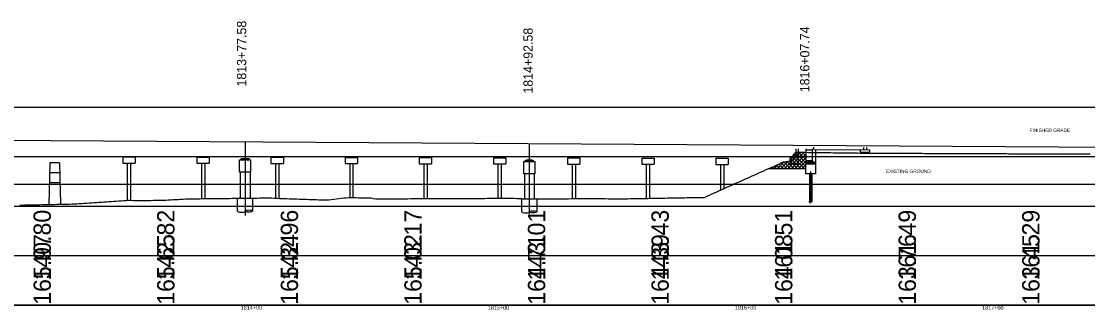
# Model space of a CAD drawing. Extents: x 2126510 to 2136144, y 865066 to 868066.
# Drawn here: x 2129755.8 to 2130187.2, y 866612.1 to 866728.8 of the extents above; entities that cross this region are included whole.
import ezdxf

# ---------------------------------------------------------------- set-up
doc = ezdxf.new("R2010")
doc.units = 0
for name, color, linetype in [('RD_DTM_BkLn1', 7, 'Continuous'), ('RD_EX_Bldg', 7, 'Continuous'), ('RD_EX_Bridge', 7, 'Continuous'), ('RD_EX_DR_Pipe', 7, 'Continuous'), ('RD_EX_GuardRail', 7, 'Continuous'), ('RD_EX_H2O', 7, 'Continuous'), ('RD_EX_Misc', 7, 'Continuous'), ('RD_EX_Misc_Golf_Fairway', 7, 'Continuous'), ('RD_HC_Data', 7, 'Continuous'), ('RD_HC_txCode', 7, 'Continuous')]:
    doc.layers.add(name, color=color, linetype=linetype)

msp = doc.modelspace()

# ---------------------------------------------------------------- linework, layer by layer
at = {"layer": 'RD_DTM_BkLn1'}
for p, q in [((2130076.46, 866676.93), (2130076.46, 866677.93)), ((2130096.46, 866677.81), (2130096.46, 866676.81)), ((2130097.71, 866677.81), (2130097.71, 866676.81)), ((2129848.04, 866673.11), (2129844.54, 866673.11)), ((2129844.54, 866673.11), (2129844.54, 866672.78)), ((2129844.96, 866673.11), (2129847.63, 866673.11)), ((2129848.04, 866672.78), (2129848.04, 866673.11)), ((2129962.63, 866672.68), (2129959.96, 866672.68)), ((2130076.46, 866676.93), (2130098.96, 866676.79)), ((2130095.21, 866676.82), (2130095.21, 866675.82)), ((2130095.21, 866675.82), (2130098.96, 866675.79)), ((2130098.96, 866676.79), (2130098.96, 866675.79)), ((2129963.04, 866672.39), (2129959.54, 866672.39)), ((2129959.54, 866672.39), (2129959.54, 866672.06)), ((2129959.96, 866672.39), (2129962.63, 866672.39)), ((2129963.04, 866672.06), (2129963.04, 866672.39)), ((2130076.88, 866671.67), (2130073.38, 866671.67)), ((2130073.38, 866671.67), (2130073.38, 866671.09)), ((2130076.46, 866671.96), (2130073.79, 866671.96)), ((2130073.79, 866671.96), (2130073.79, 866671.67)), ((2130073.79, 866671.67), (2130076.46, 866671.67)), ((2130076.46, 866671.67), (2130076.46, 866671.96)), ((2130076.88, 866671.09), (2130076.88, 866671.67)), ((2129844.29, 866667.78), (2129844.29, 866657.21)), ((2129848.29, 866667.78), (2129848.29, 866657.25)), ((2129959.29, 866667.06), (2129959.29, 866656.94)), ((2129963.29, 866667.06), (2129963.29, 866656.94))]:
    msp.add_line(p, q, dxfattribs=at)
for points in [[(2129844.04, 866672.78), (2129848.54, 866672.78), (2129848.54, 866667.78), (2129844.04, 866667.78)], [(2129959.04, 866672.06), (2129963.54, 866672.06), (2129963.54, 866667.06), (2129959.04, 866667.06)], [(2130073.13, 866671.09), (2130077.13, 866671.09), (2130077.13, 866667.09), (2130073.13, 866667.09)]]:
    msp.add_lwpolyline(points, close=True, dxfattribs=at)
for points in [[(2129843.29, 866651.99), (2129843.29, 866657.23), (2129849.29, 866657.23), (2129849.29, 866651.99)], [(2129958.29, 866651.7), (2129958.29, 866656.94), (2129964.29, 866656.94), (2129964.29, 866651.7)]]:
    msp.add_lwpolyline(points, dxfattribs=at)
for centre in [(2129844.79, 866651.99), (2129959.79, 866651.7)]:
    msp.add_ellipse(centre, major_axis=(-1.5, 0), ratio=0.310397, start_param=0, end_param=3.141593, dxfattribs=at)
for centre in [(2129847.79, 866651.99), (2129962.79, 866651.7)]:
    msp.add_ellipse(centre, major_axis=(-1.5, 0), ratio=0.310397, dxfattribs=at)
at = {"layer": 'RD_EX_Bldg'}
for p, q in [((2130074.63, 866667.09), (2130074.63, 866655.74)), ((2130075.63, 866667.09), (2130075.63, 866655.74))]:
    msp.add_line(p, q, dxfattribs=at)
msp.add_lwpolyline([(2130075.92, 866655.74), (2130075.38, 866655.74), (2130075.38, 866656.32), (2130074.87, 866655.16), (2130074.87, 866655.74), (2130074.33, 866655.74)], dxfattribs=at)
at = {"layer": 'RD_EX_Bridge'}
for p, q in [((2129844.96, 866673.4), (2129844.96, 866673.11)), ((2129847.63, 866673.11), (2129847.63, 866673.4)), ((2129959.96, 866672.68), (2129959.96, 866672.39)), ((2129962.63, 866672.39), (2129962.63, 866672.68))]:
    msp.add_line(p, q, dxfattribs=at)
at = {"layer": 'RD_EX_DR_Pipe'}
for p, q in [((2130064.39, 866669.09), (2130071.11, 866675.82)), ((2130065.8, 866669.09), (2130072.51, 866675.8)), ((2130067.22, 866669.09), (2130073.13, 866675)), ((2130067.42, 866672.99), (2130071.31, 866669.09)), ((2130067.78, 866673.9), (2130069.72, 866675.84)), ((2130067.82, 866674), (2130072.73, 866669.09)), ((2130068.25, 866674.99), (2130073.13, 866670.11)), ((2130068.63, 866669.09), (2130073.13, 866673.59)), ((2130068.99, 866675.66), (2130073.13, 866671.52)), ((2130070.23, 866675.83), (2130073.13, 866672.94)), ((2130071.67, 866675.81), (2130073.13, 866674.35)), ((2130073.1, 866675.79), (2130073.13, 866675.77)), ((2130058.38, 866669.3), (2130058.59, 866669.09)), ((2130058.73, 866669.09), (2130059.39, 866669.75)), ((2130059.36, 866669.74), (2130060, 866669.09)), ((2130060.15, 866669.09), (2130061.97, 866670.92)), ((2130060.33, 866670.18), (2130061.41, 866669.09)), ((2130061.3, 866670.62), (2130062.83, 866669.09)), ((2130061.56, 866669.09), (2130064.43, 866671.96)), ((2130062.28, 866671.06), (2130064.24, 866669.09)), ((2130062.98, 866669.09), (2130066.07, 866672.19)), ((2130063.25, 866671.5), (2130065.66, 866669.09)), ((2130064.23, 866671.93), (2130067.07, 866669.09)), ((2130065.46, 866672.12), (2130068.48, 866669.09)), ((2130066.69, 866672.3), (2130069.9, 866669.09)), ((2130070.05, 866669.09), (2130073.13, 866672.17)), ((2130071.46, 866669.09), (2130073.13, 866670.76)), ((2130072.87, 866669.09), (2130073.13, 866669.35))]:
    msp.add_line(p, q, dxfattribs=at)
msp.add_lwpolyline([(2130073.13, 866669.09), (2130057.92, 866669.09)], dxfattribs=at)
at = {"layer": 'RD_EX_GuardRail'}
for p, q in [((2131097.7, 866693.9), (2126517.45, 866693.9)), ((2131097.7, 866673.9), (2129000.13, 866673.9)), ((2131097.7, 866653.9), (2126517.45, 866653.9)), ((2131097.7, 866633.9), (2126517.45, 866633.9)), ((2131097.7, 866613.9), (2126517.45, 866613.9))]:
    msp.add_line(p, q, dxfattribs=at)
at = {"layer": 'RD_EX_H2O'}
for points in [[(2130032.19, 866657.56), (2130033.19, 866658.05), (2130034.19, 866658.5), (2130035.19, 866658.95), (2130036.19, 866659.4), (2130037.19, 866659.84), (2130038.19, 866660.29), (2130039.19, 866660.74), (2130040.19, 866661.18), (2130041.19, 866661.63), (2130042.19, 866662.07), (2130043.19, 866662.52), (2130044.19, 866662.97), (2130045.19, 866663.41), (2130046.19, 866663.86), (2130047.19, 866664.31), (2130048.19, 866664.75), (2130049.19, 866665.2), (2130050.19, 866665.64), (2130051.19, 866666.09), (2130052.19, 866666.54), (2130053.19, 866666.98), (2130054.19, 866667.43), (2130055.19, 866667.88), (2130056.19, 866668.32), (2130057.19, 866668.77), (2130058.19, 866669.21), (2130059.19, 866669.66), (2130060.19, 866670.11), (2130061.19, 866670.56), (2130062.19, 866671.02), (2130063.19, 866671.47), (2130064.19, 866671.92), (2130065.19, 866672.08), (2130066.19, 866672.2), (2130067.19, 866672.4), (2130068.19, 866674.94), (2130069.19, 866675.84), (2130070.19, 866675.83), (2130071.19, 866675.82), (2130072.19, 866675.8), (2130073.19, 866675.79), (2130074.19, 866675.78), (2130075.19, 866675.76), (2130076.19, 866675.75), (2130077.19, 866675.74), (2130078.19, 866675.72), (2130079.19, 866675.71), (2130080.19, 866675.7), (2130081.19, 866675.68), (2130082.19, 866675.67), (2130083.19, 866675.66), (2130084.19, 866675.65), (2130085.19, 866675.63), (2130086.19, 866675.62), (2130087.19, 866675.61), (2130088.19, 866675.6), (2130089.19, 866675.58), (2130090.19, 866675.57), (2130091.19, 866675.56), (2130092.19, 866675.55), (2130093.19, 866675.53), (2130094.19, 866675.52), (2130095.19, 866675.51), (2130096.19, 866675.5), (2130097.19, 866675.49), (2130098.19, 866675.48), (2130099.19, 866675.48), (2130100.19, 866675.48), (2130101.19, 866675.47), (2130102.19, 866675.47), (2130103.19, 866675.47), (2130104.19, 866675.46), (2130105.19, 866675.46), (2130106.19, 866675.46), (2130107.19, 866675.46), (2130108.19, 866675.45), (2130109.19, 866675.45), (2130110.19, 866675.45), (2130111.19, 866675.44), (2130112.19, 866675.44), (2130113.19, 866675.43), (2130114.19, 866675.42), (2130115.19, 866675.42), (2130116.19, 866675.41), (2130117.19, 866675.4), (2130118.19, 866675.4), (2130119.19, 866675.39), (2130120.19, 866675.39), (2130121.19, 866675.38), (2130122.19, 866675.38), (2130123.19, 866675.38), (2130124.19, 866675.37), (2130125.19, 866675.37), (2130126.19, 866675.36), (2130127.19, 866675.36), (2130128.19, 866675.36), (2130129.19, 866675.35), (2130130.19, 866675.35), (2130131.19, 866675.34), (2130132.19, 866675.34)], [(2130132.19, 866675.34), (2130133.19, 866675.34), (2130134.19, 866675.33), (2130135.19, 866675.33), (2130136.19, 866675.32), (2130137.19, 866675.32), (2130138.19, 866675.32), (2130139.19, 866675.31), (2130140.19, 866675.31), (2130141.19, 866675.3), (2130142.19, 866675.3), (2130143.19, 866675.29), (2130144.19, 866675.29), (2130145.19, 866675.29), (2130146.19, 866675.28), (2130147.19, 866675.28), (2130148.19, 866675.27), (2130149.19, 866675.27), (2130150.19, 866675.27), (2130151.19, 866675.26), (2130152.19, 866675.26), (2130153.19, 866675.25), (2130154.19, 866675.25), (2130155.19, 866675.24), (2130156.19, 866675.24), (2130157.19, 866675.23), (2130158.19, 866675.23), (2130159.19, 866675.22), (2130160.19, 866675.22), (2130161.19, 866675.21), (2130162.19, 866675.21), (2130163.19, 866675.21), (2130164.19, 866675.21), (2130165.19, 866675.2), (2130166.19, 866675.2), (2130167.19, 866675.2), (2130168.19, 866675.19), (2130169.19, 866675.19), (2130170.19, 866675.19), (2130171.19, 866675.19), (2130172.19, 866675.18), (2130173.19, 866675.18), (2130174.19, 866675.18), (2130175.19, 866675.18), (2130176.19, 866675.17), (2130177.19, 866675.17), (2130178.19, 866675.17), (2130179.19, 866675.17), (2130180.19, 866675.16), (2130181.19, 866675.16), (2130182.19, 866675.17), (2130183.19, 866675.17), (2130184.19, 866675.17), (2130185.19, 866675.18), (2130186.19, 866675.18), (2130187.19, 866675.18), (2130188.19, 866675.19)], [(2129755.19, 866654.47), (2129756.19, 866654.45), (2129757.19, 866654.47), (2129758.19, 866654.49), (2129759.19, 866654.51), (2129760.19, 866654.53), (2129761.19, 866654.55), (2129762.19, 866654.57), (2129763.19, 866654.59), (2129764.19, 866654.61), (2129765.19, 866654.63), (2129766.19, 866654.65), (2129767.19, 866654.67), (2129768.19, 866654.69), (2129769.19, 866654.72), (2129770.19, 866654.74), (2129771.19, 866654.76), (2129772.19, 866654.78), (2129773.19, 866654.77), (2129774.19, 866654.76), (2129775.19, 866654.8), (2129776.19, 866654.9), (2129777.19, 866654.92), (2129778.19, 866654.95), (2129779.19, 866655.02), (2129780.19, 866655.09), (2129781.19, 866655.16), (2129782.19, 866655.23), (2129783.19, 866655.3), (2129784.19, 866655.37), (2129785.19, 866655.44), (2129786.19, 866655.51), (2129787.19, 866655.58), (2129788.19, 866655.65), (2129789.19, 866655.71), (2129790.19, 866655.78), (2129791.19, 866655.85), (2129792.19, 866655.92), (2129793.19, 866655.99), (2129794.19, 866656.06), (2129795.19, 866656.13), (2129796.19, 866656.2), (2129797.19, 866656.27), (2129798.19, 866656.34), (2129799.19, 866656.41), (2129800.19, 866656.44), (2129801.19, 866656.31), (2129802.19, 866656.31), (2129803.19, 866656.32), (2129804.19, 866656.33), (2129805.19, 866656.33), (2129806.19, 866656.34), (2129807.19, 866656.35), (2129808.19, 866656.35), (2129809.19, 866656.36), (2129810.19, 866656.36), (2129811.19, 866656.36), (2129812.19, 866656.36), (2129813.19, 866656.42), (2129814.19, 866656.47), (2129815.19, 866656.53), (2129816.19, 866656.58), (2129817.19, 866656.64), (2129818.19, 866656.69), (2129819.19, 866656.75), (2129820.19, 866656.8), (2129821.19, 866656.86), (2129822.19, 866656.9), (2129823.19, 866656.92), (2129824.19, 866656.95), (2129825.19, 866656.97), (2129826.19, 866656.99), (2129827.19, 866657), (2129828.19, 866657.02), (2129829.19, 866657.04), (2129830.19, 866657.06), (2129831.19, 866657.07), (2129832.19, 866657.08)], [(2129832.19, 866657.08), (2129833.19, 866657.08), (2129834.19, 866657.09), (2129835.19, 866657.1), (2129836.19, 866657.12), (2129837.19, 866657.13), (2129838.19, 866657.14), (2129839.19, 866657.15), (2129840.19, 866657.16), (2129841.19, 866657.17), (2129842.19, 866657.18), (2129843.19, 866657.2), (2129844.19, 866657.21), (2129845.19, 866657.22), (2129846.19, 866657.23), (2129847.19, 866657.24), (2129848.19, 866657.25), (2129849.19, 866657.26), (2129850.19, 866657.28), (2129851.19, 866657.29), (2129852.19, 866657.3), (2129853.19, 866657.31), (2129854.19, 866657.32), (2129855.19, 866657.34), (2129856.19, 866657.32), (2129857.19, 866657.31), (2129858.19, 866657.24), (2129859.19, 866657.19), (2129860.19, 866657.15), (2129861.19, 866657.12), (2129862.19, 866657.09), (2129863.19, 866657.05), (2129864.19, 866657.02), (2129865.19, 866656.98), (2129866.19, 866656.95), (2129867.19, 866656.91), (2129868.19, 866656.88), (2129869.19, 866656.84), (2129870.19, 866656.81), (2129871.19, 866656.77), (2129872.19, 866656.74), (2129873.19, 866656.71), (2129874.19, 866656.67), (2129875.19, 866656.64), (2129876.19, 866656.6), (2129877.19, 866656.57), (2129878.19, 866656.53), (2129879.19, 866656.5), (2129880.19, 866656.6), (2129881.19, 866656.72), (2129882.19, 866656.84), (2129883.19, 866656.95), (2129884.19, 866657.07), (2129885.19, 866657.18), (2129886.19, 866657.3), (2129887.19, 866657.42), (2129888.19, 866657.48), (2129889.19, 866657.47), (2129890.19, 866657.45), (2129891.19, 866657.44), (2129892.19, 866657.43), (2129893.19, 866657.41), (2129894.19, 866657.4), (2129895.19, 866657.38), (2129896.19, 866657.37), (2129897.19, 866657.31), (2129898.19, 866657.15), (2129899.19, 866656.99), (2129900.19, 866656.93), (2129901.19, 866656.94), (2129902.19, 866656.94), (2129903.19, 866656.95), (2129904.19, 866656.96), (2129905.19, 866656.97), (2129906.19, 866656.97), (2129907.19, 866656.98), (2129908.19, 866656.99), (2129909.19, 866657), (2129910.19, 866657), (2129911.19, 866657.01), (2129912.19, 866657.02), (2129913.19, 866657.03), (2129914.19, 866657.03), (2129915.19, 866657.04), (2129916.19, 866657.05), (2129917.19, 866657.06), (2129918.19, 866657.07), (2129919.19, 866657.07), (2129920.19, 866657.07), (2129921.19, 866657.06), (2129922.19, 866657.07), (2129923.19, 866657.07), (2129924.19, 866657.08), (2129925.19, 866657.08), (2129926.19, 866657.09), (2129927.19, 866657.09), (2129928.19, 866657.1), (2129929.19, 866657.1), (2129930.19, 866657.11), (2129931.19, 866657.11), (2129932.19, 866657.11)], [(2129932.19, 866657.11), (2129933.19, 866657.12), (2129934.19, 866657.12), (2129935.19, 866657.13), (2129936.19, 866657.13), (2129937.19, 866657.14), (2129938.19, 866657.14), (2129939.19, 866657.15), (2129940.19, 866657.15), (2129941.19, 866657.16), (2129942.19, 866657.16), (2129943.19, 866657.16), (2129944.19, 866657.17), (2129945.19, 866657.17), (2129946.19, 866657.18), (2129947.19, 866657.18), (2129948.19, 866657.19), (2129949.19, 866657.2), (2129950.19, 866657.21), (2129951.19, 866657.22), (2129952.19, 866657.22), (2129953.19, 866657.23), (2129954.19, 866657.24), (2129955.19, 866657.2), (2129956.19, 866657.14), (2129957.19, 866657.09), (2129958.19, 866657.03), (2129959.19, 866656.98), (2129960.19, 866656.95), (2129961.19, 866656.94), (2129962.19, 866656.93), (2129963.19, 866656.93), (2129964.19, 866656.92), (2129965.19, 866656.91), (2129966.19, 866656.91), (2129967.19, 866656.91), (2129968.19, 866656.91), (2129969.19, 866656.92), (2129970.19, 866656.93), (2129971.19, 866656.94), (2129972.19, 866656.95), (2129973.19, 866656.95), (2129974.19, 866656.96), (2129975.19, 866656.98), (2129976.19, 866656.99), (2129977.19, 866657.01), (2129978.19, 866657.03), (2129979.19, 866657.05), (2129980.19, 866657.05), (2129981.19, 866657.05), (2129982.19, 866657.05), (2129983.19, 866657.05), (2129984.19, 866657.04), (2129985.19, 866657.04), (2129986.19, 866657.04), (2129987.19, 866657.04), (2129988.19, 866657.04), (2129989.19, 866657.04), (2129990.19, 866657.04), (2129991.19, 866657.04), (2129992.19, 866657.03), (2129993.19, 866657), (2129994.19, 866656.98), (2129995.19, 866656.96), (2129996.19, 866656.93), (2129997.19, 866656.91), (2129998.19, 866656.93), (2129999.19, 866656.96), (2130000.19, 866656.99), (2130001.19, 866657.01), (2130002.19, 866657.04), (2130003.19, 866657.06), (2130004.19, 866657.08), (2130005.19, 866657.1), (2130006.19, 866657.11), (2130007.19, 866657.13), (2130008.19, 866657.15), (2130009.19, 866657.16), (2130010.19, 866657.18), (2130011.19, 866657.2), (2130012.19, 866657.22), (2130013.19, 866657.23), (2130014.19, 866657.25), (2130015.19, 866657.27), (2130016.19, 866657.28), (2130017.19, 866657.3), (2130018.19, 866657.32), (2130019.19, 866657.34), (2130020.19, 866657.35), (2130021.19, 866657.37), (2130022.19, 866657.39), (2130023.19, 866657.4), (2130024.19, 866657.42), (2130025.19, 866657.44), (2130026.19, 866657.46), (2130027.19, 866657.47), (2130028.19, 866657.49), (2130029.19, 866657.51), (2130030.19, 866657.52), (2130031.19, 866657.47), (2130032.19, 866657.56)]]:
    msp.add_lwpolyline(points, dxfattribs=at)
at = {"layer": 'RD_EX_Misc'}
for p, q in [((2129494.88, 866682.29), (2130513.48, 866675.88)), ((2127368.72, 866613.9), (2131522.97, 866613.9))]:
    msp.add_line(p, q, dxfattribs=at)
msp.add_lwpolyline([(2127275.85, 866613.9), (2127275.85, 866662.9), (2131989.68, 866662.9)], dxfattribs=at)
at = {"layer": 'RD_EX_Misc_Golf_Fairway'}
for p, q in [((2130069.28, 866673.51), (2130069.28, 866677.26)), ((2130070.28, 866671.01), (2130070.28, 866677.26)), ((2129796.78, 866673.9), (2129796.78, 866671.4)), ((2129796.78, 866673.9), (2129801.78, 866673.9)), ((2129801.78, 866673.9), (2129801.78, 866671.4)), ((2129826.78, 866673.84), (2129826.78, 866671.34)), ((2129826.78, 866673.84), (2129831.78, 866673.84)), ((2129831.78, 866673.84), (2129831.78, 866671.34)), ((2129856.78, 866673.78), (2129856.78, 866671.28)), ((2129856.78, 866673.78), (2129861.78, 866673.78)), ((2129861.78, 866673.78), (2129861.78, 866671.28)), ((2129886.78, 866673.72), (2129886.78, 866671.22)), ((2129886.78, 866673.72), (2129891.78, 866673.72)), ((2129891.78, 866673.72), (2129891.78, 866671.22)), ((2129916.78, 866673.66), (2129916.78, 866671.16)), ((2129916.78, 866673.66), (2129921.78, 866673.66)), ((2129921.78, 866673.66), (2129921.78, 866671.16)), ((2129946.78, 866673.6), (2129946.78, 866671.1)), ((2129946.78, 866673.6), (2129951.78, 866673.6)), ((2129951.78, 866673.6), (2129951.78, 866671.1)), ((2129976.78, 866673.54), (2129976.78, 866671.04)), ((2129976.78, 866673.54), (2129981.78, 866673.54)), ((2129981.78, 866673.54), (2129981.78, 866671.04)), ((2130006.78, 866673.48), (2130006.78, 866670.98)), ((2130006.78, 866673.48), (2130011.78, 866673.48)), ((2130011.78, 866673.48), (2130011.78, 866670.98)), ((2130036.78, 866673.42), (2130036.78, 866670.92)), ((2130036.78, 866673.42), (2130041.78, 866673.42)), ((2130041.78, 866673.42), (2130041.78, 866670.92)), ((2130066.78, 866671.01), (2130066.78, 866673.51)), ((2130070.28, 866673.51), (2130066.78, 866673.51)), ((2129767.28, 866671.47), (2129766.93, 866654.67)), ((2129771.28, 866671.47), (2129767.28, 866671.47)), ((2129771.28, 866671.47), (2129771.63, 866654.77)), ((2129796.78, 866671.4), (2129801.78, 866671.4)), ((2129798.62, 866671.4), (2129798.62, 866656.37)), ((2129799.95, 866671.4), (2129799.95, 866656.44)), ((2129826.78, 866671.34), (2129831.78, 866671.34)), ((2129828.62, 866671.34), (2129828.62, 866657.03)), ((2129829.95, 866671.34), (2129829.95, 866657.05)), ((2129856.78, 866671.28), (2129861.78, 866671.28)), ((2129858.62, 866671.28), (2129858.62, 866657.22)), ((2129859.95, 866671.28), (2129859.95, 866657.16)), ((2129886.78, 866671.22), (2129891.78, 866671.22)), ((2129888.62, 866671.22), (2129888.62, 866657.48)), ((2129889.95, 866671.22), (2129889.95, 866657.46)), ((2129916.78, 866671.16), (2129921.78, 866671.16)), ((2129918.62, 866671.16), (2129918.62, 866657.07)), ((2129919.95, 866671.16), (2129919.95, 866657.07)), ((2129946.78, 866671.1), (2129951.78, 866671.1)), ((2129948.62, 866671.1), (2129948.62, 866657.19)), ((2129949.95, 866671.1), (2129949.95, 866657.2)), ((2129976.78, 866671.04), (2129981.78, 866671.04)), ((2129978.62, 866671.04), (2129978.62, 866657.04)), ((2129979.95, 866671.04), (2129979.95, 866657.05)), ((2130006.78, 866670.98), (2130011.78, 866670.98)), ((2130008.62, 866670.98), (2130008.62, 866657.15)), ((2130009.95, 866670.98), (2130009.95, 866657.18)), ((2130036.78, 866670.92), (2130041.78, 866670.92)), ((2130038.62, 866670.92), (2130038.62, 866660.48)), ((2130039.95, 866670.92), (2130039.95, 866661.08)), ((2130070.28, 866671.01), (2130066.78, 866671.01)), ((2129771.37, 866667.47), (2129767.21, 866667.47)), ((2129771.45, 866663.47), (2129767.12, 866663.47))]:
    msp.add_line(p, q, dxfattribs=at)
msp.add_lwpolyline([(2130069.2, 866671.01), (2130069.2, 866671.18), (2130067.87, 866671.18), (2130067.87, 866671.01)], dxfattribs=at)
at = {"layer": 'RD_HC_Data'}
for p, q in [((2129846.29, 866680.08), (2129846.29, 866650.18)), ((2129961.29, 866679.35), (2129961.29, 866650.69)), ((2130075.13, 866668.02), (2130075.13, 866655.74))]:
    msp.add_line(p, q, dxfattribs=at)
at = {"layer": 'RD_HC_txCode'}
for p, q in [((2130073.13, 866677.23), (2130073.13, 866671.09)), ((2130075.79, 866677.23), (2130075.79, 866671.96)), ((2130073.13, 866676.81), (2130075.79, 866676.79)), ((2130077.13, 866676.93), (2130077.13, 866671.09)), ((2130073.13, 866672.56), (2130075.79, 866672.54)), ((2130073.13, 866671.98), (2130075.79, 866671.96))]:
    msp.add_line(p, q, dxfattribs=at)

# ---------------------------------------------------------------- texts
at = {"layer": 'RD_EX_Misc'}
for s, height, p in [('1813+77.58', 3.75, (2129846.76, 866702.42)), ('1814+92.58', 3.75, (2129962.68, 866699.57)), ('1816+07.74', 3.75, (2130074.62, 866700.11)), ('140.80', 7, (2129767.72, 866623.9)), ('142.82', 7, (2129817.72, 866623.9)), ('142.96', 7, (2129867.72, 866623.9)), ('143.17', 7, (2129917.72, 866623.9)), ('143.01', 7, (2129967.72, 866623.9)), ('143.43', 7, (2130017.72, 866623.9)), ('161.51', 7, (2130067.72, 866623.9)), ('161.49', 7, (2130117.72, 866623.9)), ('161.29', 7, (2130167.72, 866623.9)), ('165.97', 7, (2129767.72, 866614.05)), ('165.65', 7, (2129817.72, 866614.05)), ('165.34', 7, (2129867.72, 866614.05)), ('165.02', 7, (2129917.72, 866614.05)), ('164.71', 7, (2129967.72, 866614.05)), ('164.39', 7, (2130017.72, 866614.05)), ('164.08', 7, (2130067.72, 866614.05)), ('163.76', 7, (2130117.72, 866614.05)), ('163.45', 7, (2130167.72, 866614.05))]:
    msp.add_text(s, height=height, rotation=90, dxfattribs=at).set_placement(p)
for s, height, p in [('FINISHED GRADE', 1.4, (2130163.71, 866684.03)), ('EXISTING GROUND', 1.4, (2130105.58, 866667.41)), ('1814+00', 1.6, (2129844.51, 866612.1)), ('1815+00', 1.6, (2129944.51, 866612.1)), ('1816+00', 1.6, (2130044.51, 866612.1)), ('1817+00', 1.6, (2130144.51, 866612.1))]:
    msp.add_text(s, height=height, dxfattribs=at).set_placement(p)

doc.saveas('drawing.dxf')
